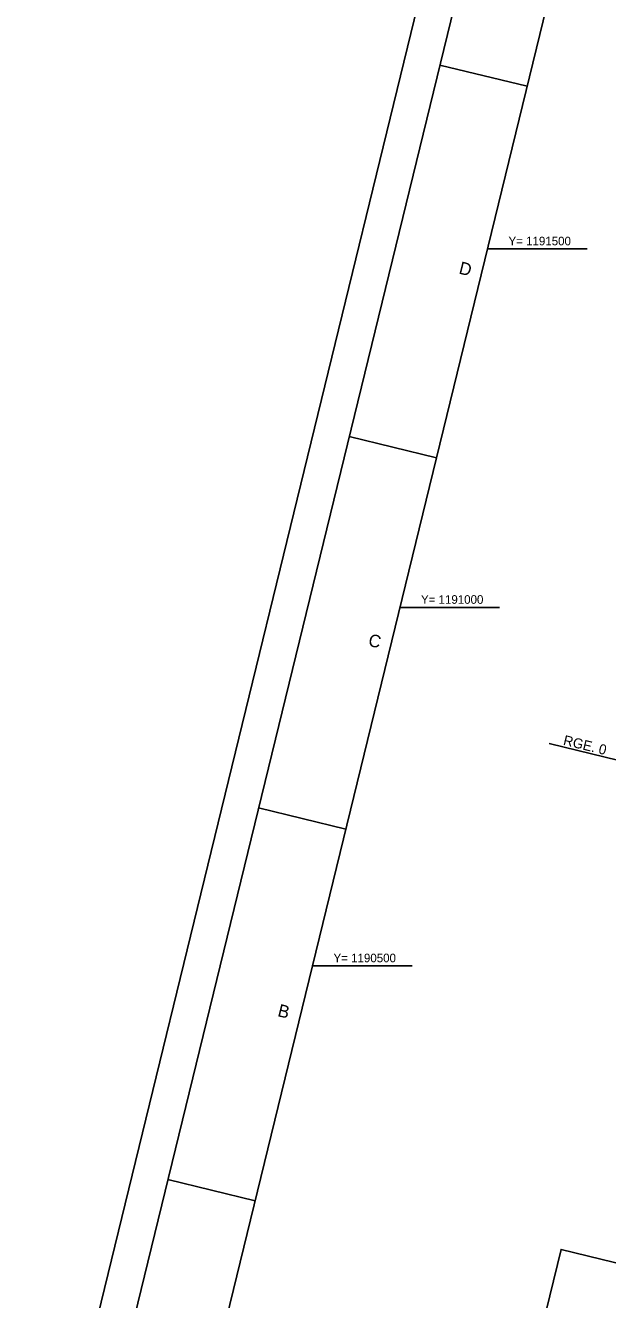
# Model space of a CAD drawing. Extents: x 409260 to 414340, y 1188556 to 1192902.
# Drawn here: x 409260 to 410071, y 1190035 to 1191812 of the extents above; entities that cross this region are included whole.
import ezdxf

# ---------------------------------------------------------------- set-up
doc = ezdxf.new("R2010")
doc.units = 0
for name, color, linetype in [('G-ANNO-NPLT', 7, 'Continuous'), ('G-ANNO-TTLB', 7, 'Continuous'), ('V-ALGN-TEXT', 7, 'Continuous'), ('V-ANNO-MATC', 7, 'Continuous'), ('V-TOPO-COOR-STAT', 7, 'Continuous')]:
    doc.layers.add(name, color=color, linetype=linetype)

msp = doc.modelspace()

# ---------------------------------------------------------------- linework, layer by layer
at = {"layer": 'G-ANNO-NPLT'}
msp.add_lwpolyline([(410065.6, 1192901.9), (414340.3, 1191859.4), (413534.7, 1188556.2), (409260, 1189598.7)], close=True, dxfattribs=at)
at = {"layer": 'G-ANNO-TTLB'}
for p, q in [((409837.7, 1191756.5), (409959.1, 1191726.8)), ((409711.4, 1191238.3), (409832.8, 1191208.7)), ((409585, 1190720.2), (409706.4, 1190690.6)), ((409458.6, 1190202.1), (409580.1, 1190172.5))]:
    msp.add_line(p, q, dxfattribs=at)
for points in [[(409320.4, 1189635.4), (413498, 1188616.6), (414279.8, 1191822.7), (410102.3, 1192841.4)], [(414219.4, 1191785.9), (410211.9, 1192763.3), (409453.7, 1189654.4), (413461.3, 1188677.1)]]:
    msp.add_lwpolyline(points, close=True, dxfattribs=at)
at = {"layer": 'V-ALGN-TEXT'}
msp.add_line((409989.9, 1190810.2), (410087.1, 1190786.6), dxfattribs=at)
at = {"layer": 'V-ANNO-MATC'}
msp.add_lwpolyline([(411682.7, 1189695.8), (410006.7, 1190104.6), (409916.8, 1189735.6), (411592.7, 1189326.9)], close=True, dxfattribs=at)
at = {"layer": 'V-TOPO-COOR-STAT'}
for p, q in [((409903.8, 1191500), (410042.8, 1191500)), ((409781.9, 1191000), (409920.8, 1191000)), ((409660, 1190500), (409798.9, 1190500))]:
    msp.add_line(p, q, dxfattribs=at)

# ---------------------------------------------------------------- texts
at = {"layer": 'G-ANNO-TTLB'}
for s, p in [('D', (409863.1, 1191465.7)), ('C', (409736.7, 1190946.7)), ('B', (409610.5, 1190430))]:
    msp.add_text(s, height=17.5, rotation=346.2946, dxfattribs=at).set_placement(p)
at = {"layer": 'V-ALGN-TEXT'}
msp.add_text('RGE. 0', height=13.92, rotation=346.2946, dxfattribs=at).set_placement((410008.7, 1190808.5))
at = {"layer": 'V-TOPO-COOR-STAT'}
for s, p in [('Y= 1191500', (409933.3, 1191505)), ('Y= 1191000', (409811.3, 1191005)), ('Y= 1190500', (409689.4, 1190505))]:
    msp.add_text(s, height=12, dxfattribs=at).set_placement(p)

doc.saveas('drawing.dxf')
